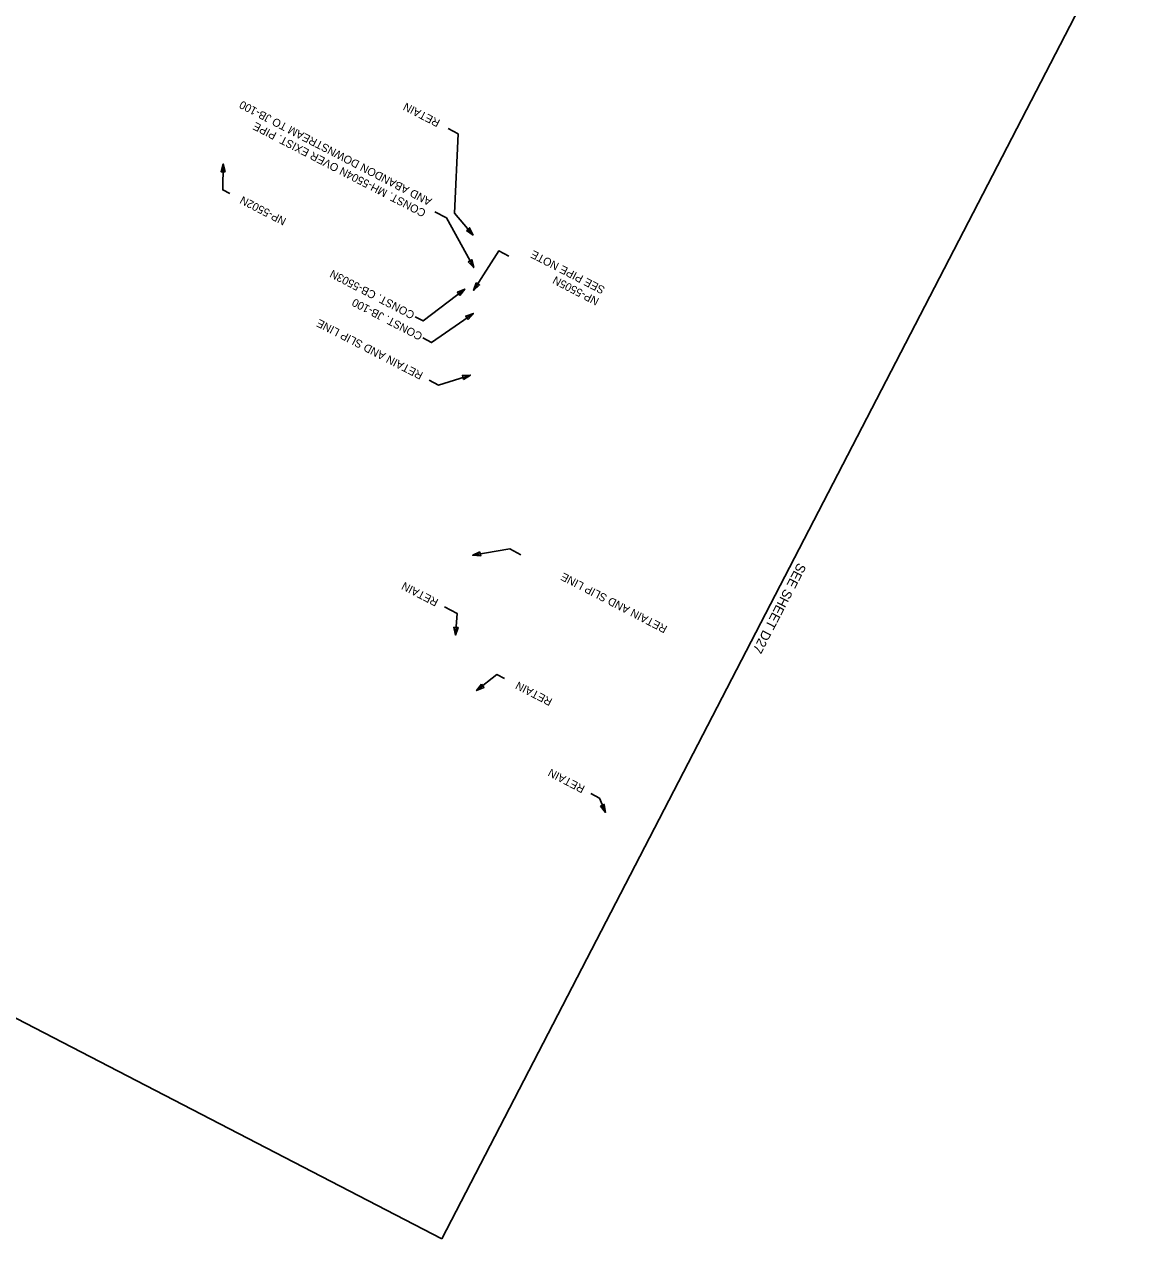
# Model space of a CAD drawing. Extents: x 1606408 to 1608529, y 1094514 to 1096115.
# Drawn here: x 1607526 to 1608216, y 1094514 to 1095273 of the extents above; entities that cross this region are included whole.
import ezdxf

# ---------------------------------------------------------------- set-up
doc = ezdxf.new("R2010")
doc.units = 0
for name, color, linetype in [('RD_HC_TX_Sta50', 7, 'Continuous'), ('RD_HY_Area_SS1', 7, 'Continuous'), ('RD_Sketch9', 7, 'Continuous')]:
    doc.layers.add(name, color=color, linetype=linetype)

msp = doc.modelspace()

# ---------------------------------------------------------------- linework, layer by layer
at = {"layer": 'RD_HC_TX_Sta50'}
msp.add_lwpolyline([(1607787.22, 1094514.3), (1606590.87, 1095133.71), (1606603.33, 1095157.78), (1606467.99, 1095228.74), (1606883.79, 1096031.81), (1608215.84, 1095342.14)], close=True, dxfattribs=at)
msp.add_lwpolyline([(1607787.22, 1094514.3), (1606590.87, 1095133.71), (1606603.33, 1095157.78), (1606467.99, 1095228.74), (1606883.79, 1096031.81), (1608215.84, 1095342.14)], close=True, dxfattribs=at)
msp.add_lwpolyline([(1607787.22, 1094514.3), (1606590.87, 1095133.71), (1606603.33, 1095157.78), (1606467.99, 1095228.74), (1606883.79, 1096031.81), (1608215.84, 1095342.14)], close=True, dxfattribs=at)
msp.add_lwpolyline([(1607787.22, 1094514.3), (1606590.87, 1095133.71), (1606603.33, 1095157.78), (1606467.99, 1095228.74), (1606883.79, 1096031.81), (1608215.84, 1095342.14)], close=True, dxfattribs=at)
msp.add_lwpolyline([(1607787.22, 1094514.3), (1606590.87, 1095133.71), (1606603.33, 1095157.78), (1606467.99, 1095228.74), (1606883.79, 1096031.81), (1608215.84, 1095342.14)], close=True, dxfattribs=at)
msp.add_lwpolyline([(1607787.22, 1094514.3), (1606590.87, 1095133.71), (1606603.33, 1095157.78), (1606467.99, 1095228.74), (1606883.79, 1096031.81), (1608215.84, 1095342.14)], close=True, dxfattribs=at)
at = {"layer": 'RD_Sketch9'}
for points in [[(1607791.2, 1095207.85), (1607797.56, 1095204.56), (1607795.19, 1095154.96), (1607806.8, 1095141.4)], [(1607654.84, 1095167.25), (1607650.34, 1095169.58), (1607650.65, 1095185.75)], [(1607782.94, 1095155.8), (1607790.2, 1095152.04), (1607807.22, 1095121.06)], [(1607829.18, 1095128.14), (1607822.85, 1095131.42), (1607807.14, 1095106.82)], [(1607770.51, 1095090.36), (1607775.66, 1095087.69), (1607801.61, 1095107.59)], [(1607775.41, 1095077.07), (1607780.89, 1095074.24), (1607806.94, 1095092.42)], [(1607779.27, 1095050.74), (1607785.27, 1095047.63), (1607805.07, 1095053.92)], [(1607836.55, 1094941.67), (1607829.66, 1094945.23), (1607806.55, 1094941.34)], [(1607788.87, 1094909.02), (1607796.77, 1094904.93), (1607795.79, 1094891.46)], [(1607826.38, 1094864.33), (1607821.67, 1094866.77), (1607808.96, 1094856.81)], [(1607880.43, 1094792.4), (1607885.73, 1094789.65), (1607889.43, 1094780.65)]]:
    msp.add_lwpolyline(points, dxfattribs=at)
for points in [[(1607651.85, 1095180.9), (1607650.65, 1095185.75), (1607649.26, 1095180.94)], [(1607802.67, 1095144.23), (1607806.8, 1095141.4), (1607804.64, 1095145.91)], [(1607803.76, 1095124.67), (1607807.22, 1095121.06), (1607806.02, 1095125.92)], [(1607798.57, 1095103.62), (1607801.61, 1095107.59), (1607796.99, 1095105.67)], [(1607808.65, 1095111.59), (1607807.14, 1095106.82), (1607810.83, 1095110.2)], [(1607803.72, 1095088.59), (1607806.94, 1095092.42), (1607802.24, 1095090.72)], [(1607800.86, 1095051.22), (1607805.07, 1095053.92), (1607800.07, 1095053.69)], [(1607811.1, 1094943.42), (1607806.55, 1094941.34), (1607811.53, 1094940.87)], [(1607794.85, 1094896.37), (1607795.79, 1094891.46), (1607797.43, 1094896.18)], [(1607811.96, 1094860.81), (1607808.96, 1094856.81), (1607813.56, 1094858.77)], [(1607886.39, 1094784.62), (1607889.43, 1094780.65), (1607888.79, 1094785.61)]]:
    msp.add_lwpolyline(points, close=True, dxfattribs=at)

# ---------------------------------------------------------------- texts
at = {"layer": 'RD_HY_Area_SS1'}
msp.add_text('SEE SHEET D27', height=6, rotation=242.57187, dxfattribs=at).set_placement((1608009.85, 1094937))
at = {"layer": 'RD_Sketch9'}
for s, p in [('AND ABANDON DOWNSTREAM TO JB-100', (1607781.49, 1095163.87)), ('RETAIN', (1607786.62, 1095213.04)), ('CONST. MH-5504N OVER EXIST. PIPE', (1607777.81, 1095156.76)), ('NP-5502N', (1607690.51, 1095151.59)), ('SEE PIPE NOTE', (1607889.63, 1095108.66)), ('CONST. CB-5503N', (1607770.77, 1095093.04)), ('NP-5505N', (1607885.95, 1095101.56)), ('CONST. JB-100', (1607775.67, 1095079.75)), ('RETAIN AND SLIP LINE', (1607775.98, 1095055.26)), ('RETAIN AND SLIP LINE', (1607928.6, 1094896.82)), ('RETAIN', (1607785.58, 1094913.54)), ('RETAIN', (1607856.79, 1094851.4)), ('RETAIN', (1607877.13, 1094796.92))]:
    msp.add_text(s, height=5, rotation=152.62682, dxfattribs=at).set_placement(p)

doc.saveas('drawing.dxf')
